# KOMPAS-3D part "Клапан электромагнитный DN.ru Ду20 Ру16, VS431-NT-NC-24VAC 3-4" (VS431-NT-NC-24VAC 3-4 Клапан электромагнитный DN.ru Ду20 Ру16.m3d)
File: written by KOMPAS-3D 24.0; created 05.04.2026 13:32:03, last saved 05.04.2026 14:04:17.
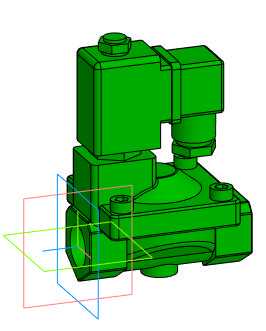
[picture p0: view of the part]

Document properties: Автор: artio; Полное имя файла: C:\Users\artio\OneDrive\Рабочий стол\Клапан электромагнитный DN.ru\VS431\VS431-NT-NC\VS431-NT-NC-24VAC\Ду20\VS431-NT-NC-24VAC 3-4 Клапан электромагнитный DN.ru Ду20 Ру16.m3d

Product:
- Body: Тело 1  | qty 1
    Масса: 1.198355
- Part/product: Клапан электромагнитный DN.ru Ду20 Ру16  | designation VS431-NT-NC-24VAC 3-4
    Масса: 0.907
    Раздел спецификации: Прочие изделия
    Примечание: D130-05508
    additional columns: ef56311e-7521-43dc-8291-0e6108b3d81d; artio; c; Шероховатость не задана; Да

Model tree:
1. Операция без истории:1

Expressions: VS431-NT-NC-24VAC 3-4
